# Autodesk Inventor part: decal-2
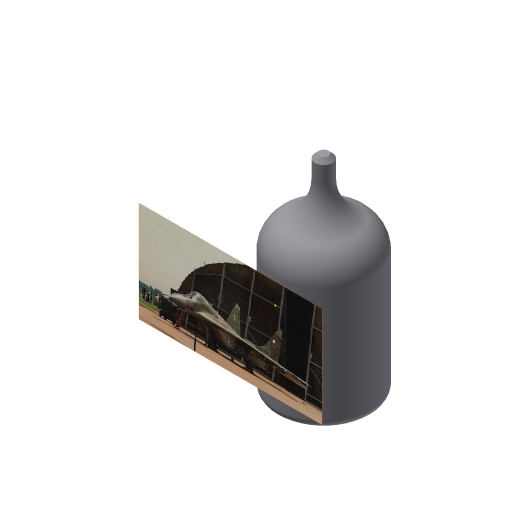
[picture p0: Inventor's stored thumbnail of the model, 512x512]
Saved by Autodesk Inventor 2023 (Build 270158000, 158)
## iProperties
Part Number: decal-2
Document SubType Name: Modeling
Created: 2002-12
Designer: deepak
Material: Generic
Density: 1 g/cm^3
Appearance: Default
Control State: 0
Master: False
Checked Out: False
Shininess: 64.0
Length Units: 11269
Angle Units: 11279
Time Units: 11290
Mass Units: 11283
Length Display Precision: 3
Angle Display Precision: 2
Compacted: True
Density: 0.0
Volumn: 0.0
Area: 0.0
PropertySet Name: Model Information
Author: deepak
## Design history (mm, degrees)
node "Sketch1"
sketch "Sketch2"
  geometry: L1 (2.054, 26.655)-(2.054, 21.177); L2 (11.64, 6.114)-(11.64, -24.209); L3 (11.64, -24.209)-(-0.098, -24.209); L4 (-0.098, -24.209)-(-0.098, 26.655); L5 (-0.098, 26.655)-(2.054, 26.655); A1 r 9.502 centre (11.556, 21.177) between (2.054, 21.177) and (7.532, 12.57); A2 r 7.127 centre (4.514, 6.114) between (11.64, 6.114) and (7.532, 12.57)
  constraints: 10 end point, 4 point on circle, 3 parallel, 3 tangent, 2 centre point, 1 perpendicular, 1 vertical
revolve "Revolution1" sketch "Sketch2" stored, may be unused: angle "d0" = 90 deg
fillet "Fillet1" dims "d1" = 2
chamfer "Chamfer1" distance "d2" = 1; stored, may be unused: second distance "d3" = 2, angle "d21" = 45 deg
workplane "Work Plane4"
sketch "Sketch7"
  geometry: L1 (-11.326, 14.075)-(33.849, 14.075); L2 (33.849, 14.075)-(33.849, -10.781); L3 (33.849, -10.781)-(-11.326, -10.781); L4 (-11.326, -10.781)-(-11.326, 14.075); 1 further point; 1 other entity
  constraints: 2 other
  node "Image6"
body "Solid1"
